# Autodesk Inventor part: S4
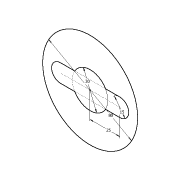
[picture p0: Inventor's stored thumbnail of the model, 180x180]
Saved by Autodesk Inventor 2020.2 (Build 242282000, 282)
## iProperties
Created: 2013-12
Part Number: S4
Material: Ogólny
Document SubType Name: Modeling
Designer: F.Stasiak
Density: 1 g/cm^3
Appearance: Domyślna
Manager: www.cadconsulting.pl
Company: Fabian Stasiak CAD Consulting
Author: F.Stasiak
Subject: Zbiór ćwiczeń. Autodesk Inventor 2020. Kurs podstawowy
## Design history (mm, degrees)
sketch "Szkic1"
  geometry: L1 (-25, 0)-(25, 0); L2 (-25, -7.5)-(-12.99, -7.5); L3 (25, 7.5)-(12.99, 7.5); L4 (12.99, -7.5)-(25, -7.5); L5 (-12.99, -7.5)-(12.99, -7.5); L6 (-12.99, 7.5)-(-25, 7.5); L7 (12.99, 7.5)-(-12.99, 7.5); C1 r 40 at (0, 0); A1 r 15 centre (0, 0) between (-15, 0) and (-12.99, -7.5); A2 r 7.5 centre (-25, 0) between (-25, 7.5) and (-25, -7.5); A3 r 7.5 centre (25, 0) between (25, -7.5) and (25, 7.5); A4 r 15 centre (0, 0) between (-12.99, 7.5) and (-15, 0); A5 r 15 centre (0, 0) between (-12.99, -7.5) and (12.99, -7.5); A6 r 15 centre (0, 0) between (12.99, -7.5) and (12.99, 7.5); A7 r 15 centre (0, 0) between (12.99, 7.5) and (-12.99, 7.5); 1 further point
  constraints: 16 end point, 14 point on circle, 12 tangent, 9 parallel, 8 centre point, 2 coincident, 1 horizontal, 1 midpoint, 1 point on line
  dimensions: "d0" = 80 diameter of C1; "d2" = 25 distance of A1.centre L1.end; "d3" = 15 diameter of A3; "d4" = 30 diameter of A7
